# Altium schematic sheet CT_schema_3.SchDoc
size 496 x 398 mm
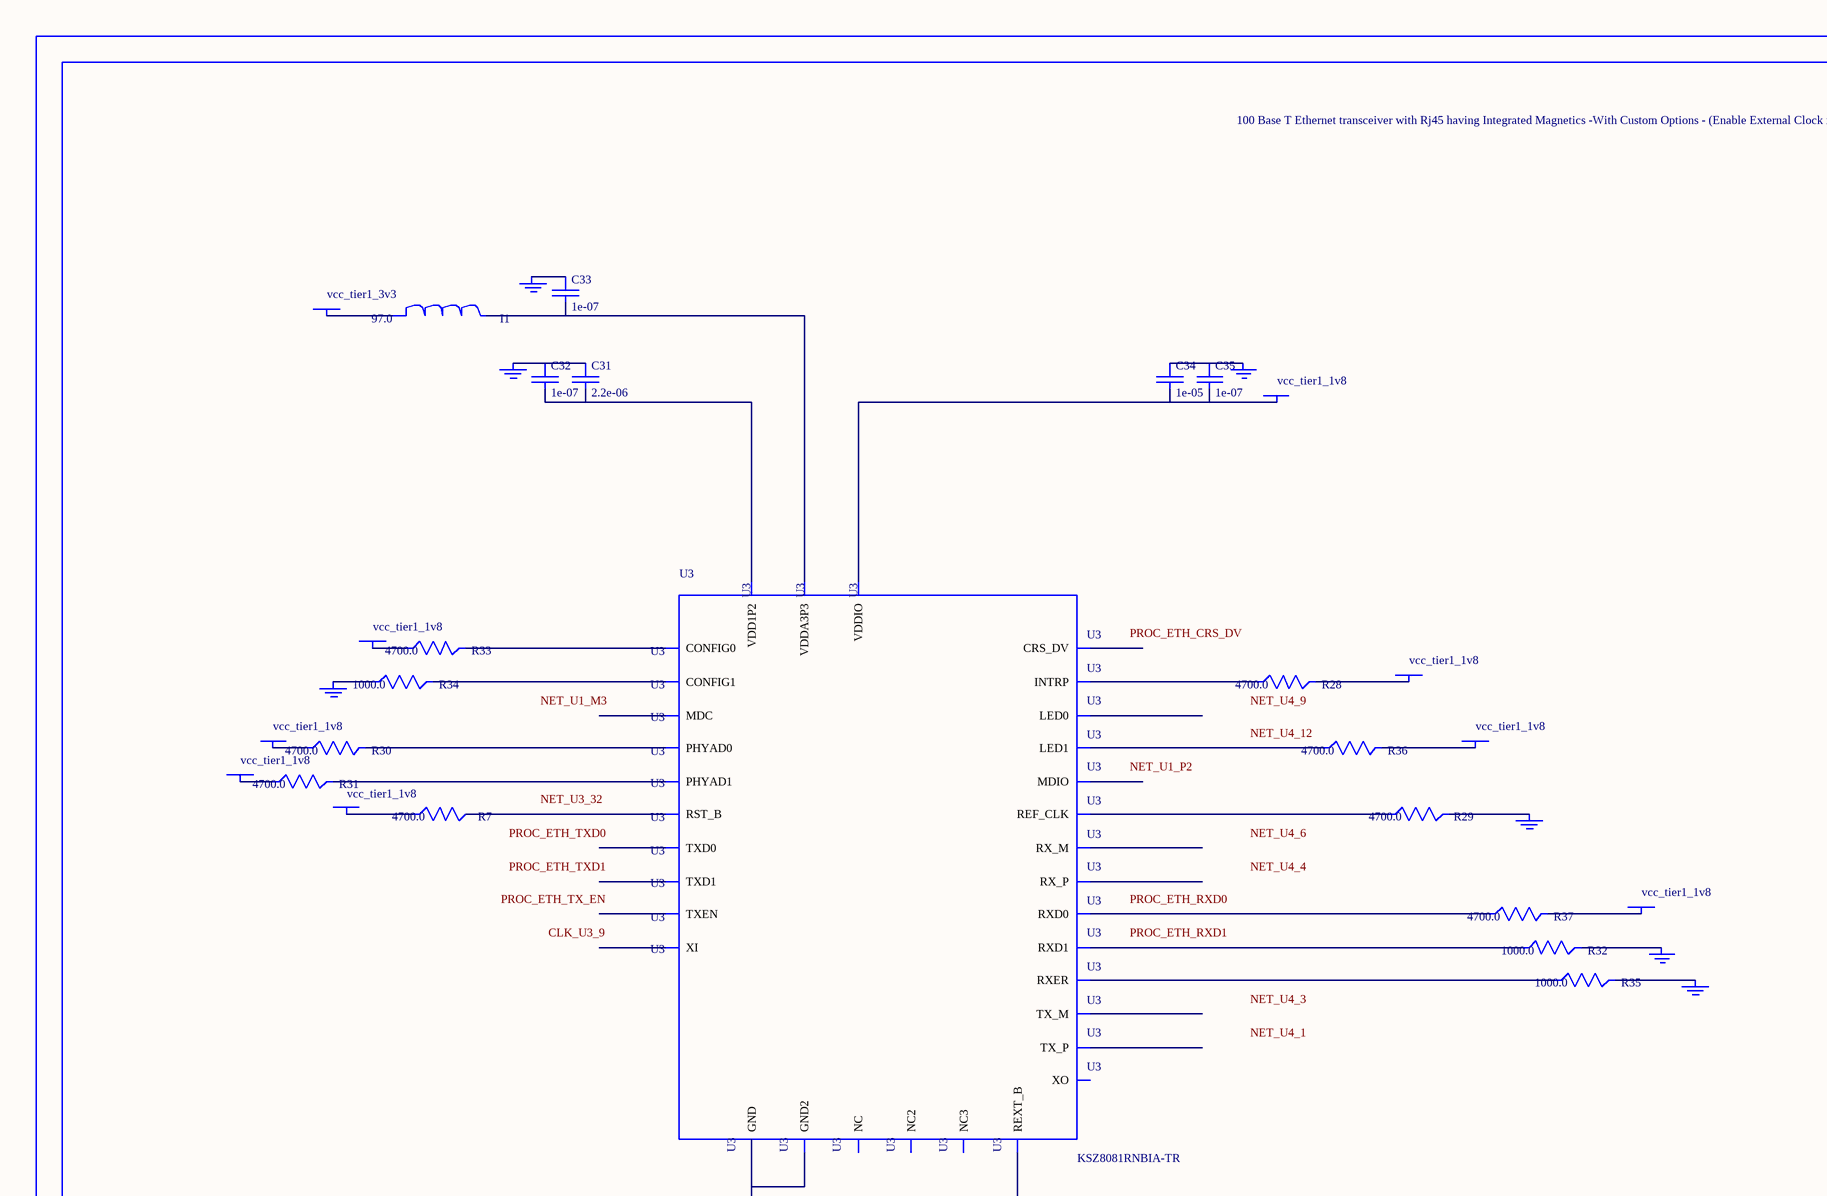
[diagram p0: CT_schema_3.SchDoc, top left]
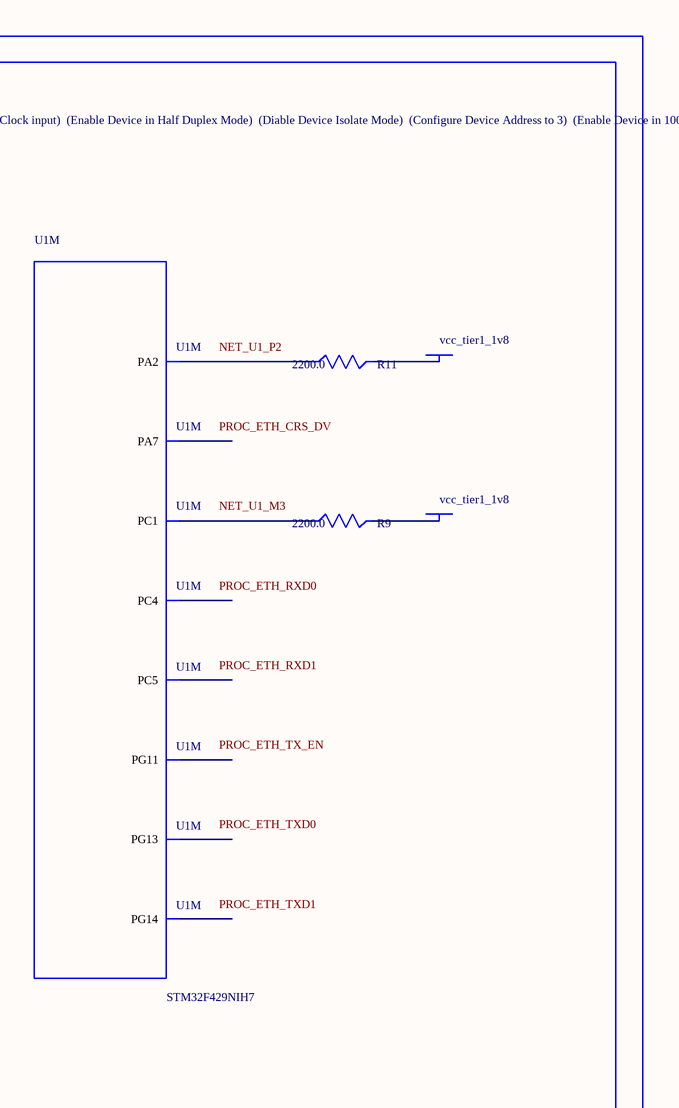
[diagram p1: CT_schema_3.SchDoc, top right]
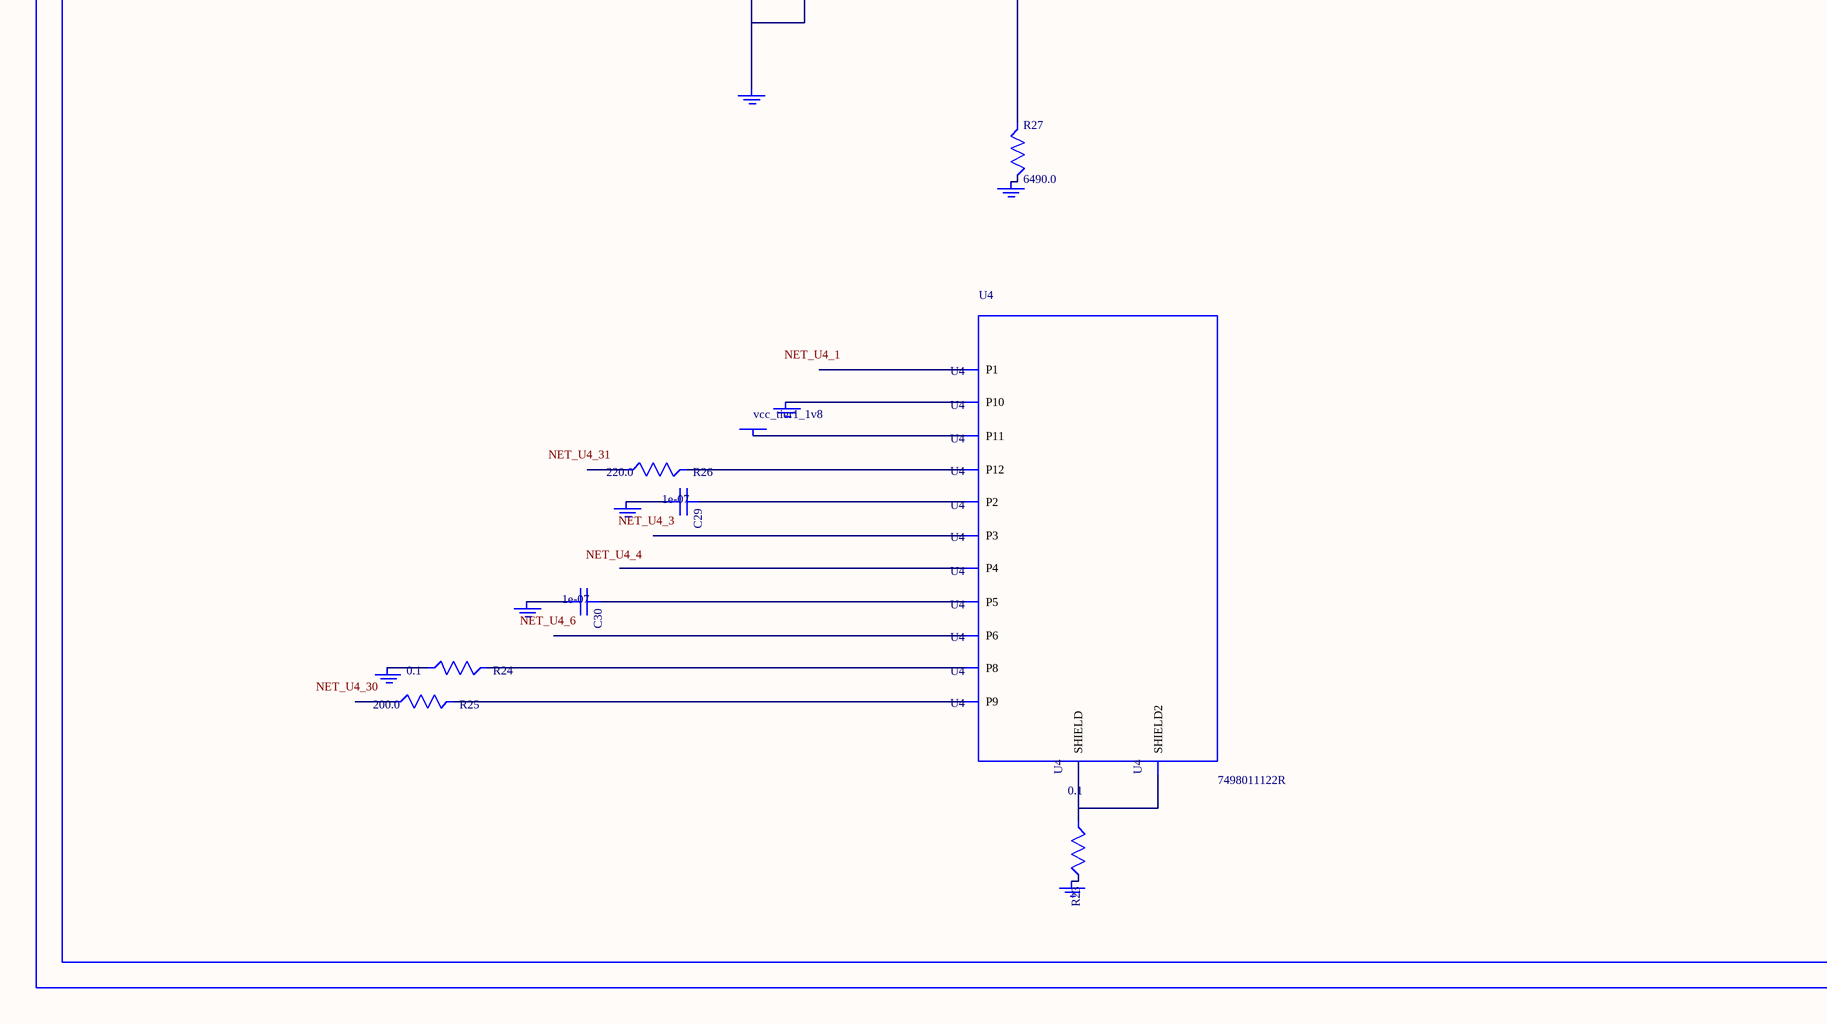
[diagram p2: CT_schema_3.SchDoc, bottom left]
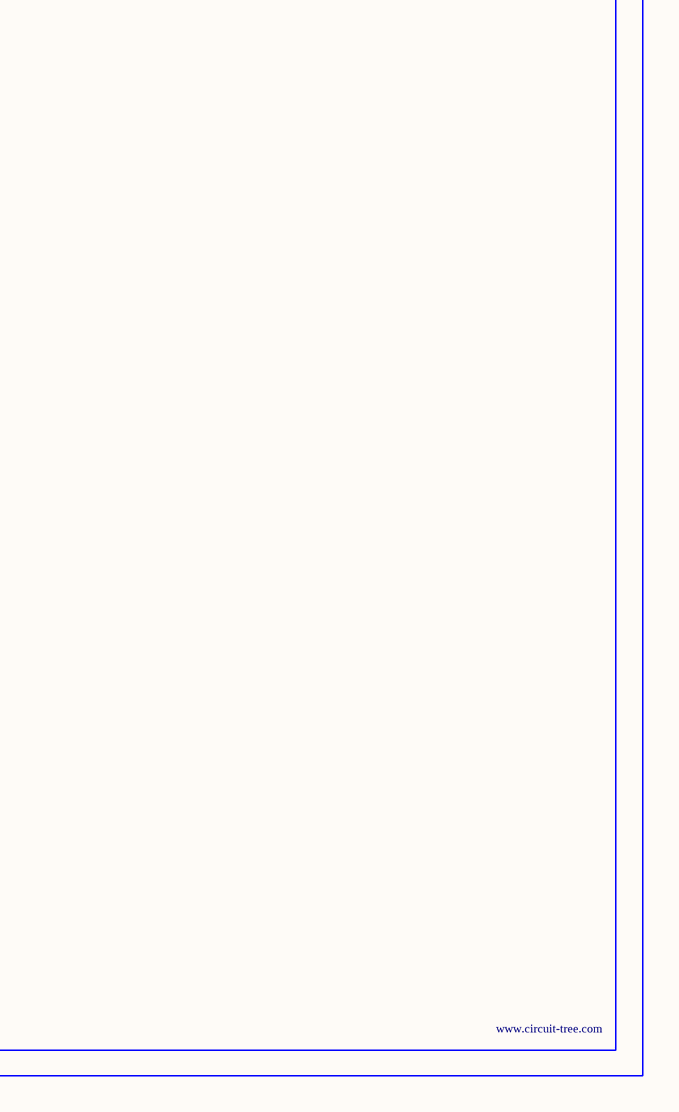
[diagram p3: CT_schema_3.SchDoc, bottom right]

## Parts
BORDER2  (no value)
C29  1e-07  [C0402]
C30  1e-07  [C0402]
C31  2.2e-06  [C0603]
C32  1e-07  [C0402]
C33  1e-07  [C0402]
C34  1e-05  [C0805]
C35  1e-07  [C0402]
GND_INSTANCE_2_0  (no value)
GND_INSTANCE_2_1  (no value)
GND_INSTANCE_2_2  (no value)
GND_INSTANCE_2_3  (no value)
GND_INSTANCE_2_4  (no value)
GND_INSTANCE_2_5  (no value)
GND_INSTANCE_2_6  (no value)
GND_INSTANCE_2_7  (no value)
GND_INSTANCE_2_8  (no value)
GND_INSTANCE_2_9  (no value)
GND_INSTANCE_2_10  (no value)
GND_INSTANCE_2_11  (no value)
GND_INSTANCE_2_12  (no value)
GND_INSTANCE_2_13  (no value)
I1  97.0  [R0603]
POWER_INSTANCE_2_0  vcc_tier1_3v3
POWER_INSTANCE_2_1  vcc_tier1_1v8
POWER_INSTANCE_2_2  vcc_tier1_1v8
POWER_INSTANCE_2_3  vcc_tier1_1v8
POWER_INSTANCE_2_4  vcc_tier1_1v8
POWER_INSTANCE_2_5  vcc_tier1_1v8
POWER_INSTANCE_2_6  vcc_tier1_1v8
POWER_INSTANCE_2_7  vcc_tier1_1v8
POWER_INSTANCE_2_8  vcc_tier1_1v8
POWER_INSTANCE_2_9  vcc_tier1_1v8
POWER_INSTANCE_2_10  vcc_tier1_1v8
POWER_INSTANCE_2_11  vcc_tier1_1v8
R7  4700.0  [R0603]
R9  2200.0  [R0603]
R11  2200.0  [R0603]
R23  0.1  [R0603]
R24  0.1  [R0603]
R25  200.0  [R0603]
R26  220.0  [R0603]
R27  6490.0  [R0603]
R28  4700.0  [R0603]
R29  4700.0  [R0603]
R30  4700.0  [R0603]
R31  4700.0  [R0603]
R32  1000.0  [R0603]
R33  4700.0  [R0603]
R34  1000.0  [R0603]
R35  1000.0  [R0603]
R36  4700.0  [R0603]
R37  4700.0  [R0603]
U1  STM32F429NIH7  [TFBGA216]  (part M of 16)
U3  KSZ8081RNBIA-TR  [QFN-32]
U4  7498011122R  [7498011122R]

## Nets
NetC29_1: C29.1 U4.2(P2)
NetC29_2: C29.2 GND_INSTANCE_2_9.0(GND)
NetC30_1: C30.1 U4.5(P5)
NetC30_2: C30.2 GND_INSTANCE_2_10.0(GND)
NetC31_1: C31.1 C32.1 GND_INSTANCE_2_0.0(GND)
NetC31_2: C31.2 C32.2 U3.2(VDD1P2)
NetC33_1: C33.1 GND_INSTANCE_2_1.0(GND)
NetC33_2: C33.2 I1.2 U3.3(VDDA3P3)
NetC34_1: C34.1 C35.1 GND_INSTANCE_2_4.0(GND)
NetC34_2: C34.2 C35.2 POWER_INSTANCE_2_4.0(PWR) U3.17(VDDIO)
NetGND_INSTANCE_2_2_0: GND_INSTANCE_2_2.0(GND) R27.2
NetGND_INSTANCE_2_3_0: GND_INSTANCE_2_3.0(GND) R32.2
NetGND_INSTANCE_2_5_0: GND_INSTANCE_2_5.0(GND) R29.2
NetGND_INSTANCE_2_6_0: GND_INSTANCE_2_6.0(GND) R35.2
NetGND_INSTANCE_2_7_0: GND_INSTANCE_2_7.0(GND) R34.1
NetGND_INSTANCE_2_8_0: GND_INSTANCE_2_8.0(GND) U3.1(GND) U3.EXP(GND2)
NetGND_INSTANCE_2_11_0: GND_INSTANCE_2_11.0(GND) R24.1
NetGND_INSTANCE_2_12_0: GND_INSTANCE_2_12.0(GND) U4.10(P10)
NetGND_INSTANCE_2_13_0: GND_INSTANCE_2_13.0(GND) R23.2
NetI1_1: I1.1 POWER_INSTANCE_2_0.0(PWR)
NetPOWER_INSTANCE_2_1_0: POWER_INSTANCE_2_1.0(PWR) R30.1
NetPOWER_INSTANCE_2_2_0: POWER_INSTANCE_2_2.0(PWR) R31.1
NetPOWER_INSTANCE_2_3_0: POWER_INSTANCE_2_3.0(PWR) R37.2
NetPOWER_INSTANCE_2_5_0: POWER_INSTANCE_2_5.0(PWR) R28.2
NetPOWER_INSTANCE_2_6_0: POWER_INSTANCE_2_6.0(PWR) R33.1
NetPOWER_INSTANCE_2_7_0: POWER_INSTANCE_2_7.0(PWR) R36.2
NetPOWER_INSTANCE_2_8_0: POWER_INSTANCE_2_8.0(PWR) R7.1
NetPOWER_INSTANCE_2_9_0: POWER_INSTANCE_2_9.0(PWR) R11.2
NetPOWER_INSTANCE_2_10_0: POWER_INSTANCE_2_10.0(PWR) R9.2
NetPOWER_INSTANCE_2_11_0: POWER_INSTANCE_2_11.0(PWR) U4.11(P11)
NetR7_2: R7.2 U3.32(RST_B)
NetR9_1: R9.1 U1.M3(PC1)
NetR11_1: R11.1 U1.P2(PA2)
NetR23_1: R23.1 U4.13(SHIELD) U4.14(SHIELD2)
NetR24_2: R24.2 U4.8(P8)
NetR25_2: R25.2 U4.9(P9)
NetR26_2: R26.2 U4.12(P12)
NetR27_1: R27.1 U3.10(REXT_B)
NetR28_1: R28.1 U3.21(INTRP)
NetR29_1: R29.1 U3.19(REF_CLK)
NetR30_2: R30.2 U3.13(PHYAD0)
NetR31_2: R31.2 U3.14(PHYAD1)
NetR32_1: R32.1 U3.15(RXD1)
NetR33_2: R33.2 U3.28(CONFIG0)
NetR34_2: R34.2 U3.29(CONFIG1)
NetR35_1: R35.1 U3.20(RXER)
NetR36_1: R36.1 U3.31(LED1)
NetR37_1: R37.1 U3.16(RXD0)

Not connected (* = marked no-connect by the designer): R25 1; R26 1; U1 A4(PG14) B3(PG13) B8(PG11) N5(PC4) P5(PC5) R3(PA7); U3 4(RX_M) 5(RX_P) 6(TX_M) 7(TX_P) 8(XO) 9(XI) 11(MDIO) 12(MDC) 18(CRS_DV) 22(NC) 23(TXEN) 24(TXD0) 25(TXD1) 26(NC2) 27(NC3) 30(LED0); U4 1(P1) 3(P3) 4(P4) 6(P6)

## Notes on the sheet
- Labels drawn without touching a wire or pin: CLK_U3_9, NET_U1_M3, NET_U1_P2, NET_U3_32, NET_U4_1, NET_U4_3, NET_U4_4, NET_U4_6, NET_U4_9, NET_U4_12, NET_U4_30, NET_U4_31, PROC_ETH_CRS_DV, PROC_ETH_RXD0, PROC_ETH_RXD1, PROC_ETH_TX_EN, PROC_ETH_TXD0, PROC_ETH_TXD1

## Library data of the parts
BORDER2 = BORDER_PAGE2
C29 C30 C32 C33 C35 = C0402C104K3RACTU
C31 = C0603C225K8RACTU
C34 = C0805C106K8RACTU
GND_INSTANCE_2_0-GND_INSTANCE_2_13 = GND
I1 = I1
POWER_INSTANCE_2_0-POWER_INSTANCE_2_11 = PWR
R7 R28-R31 R33 R36 R37 = RC0603JR-074K7L
R9 R11 = RC0603JR-072K2L
R23 R24 = ERJ-3RSFR10V
R25 = RC0603JR-07200RL
R26 = RC0603JR-07220RL
R27 = ERJ-3EKF6491V
R32 R34 R35 = RC0603JR-071KL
